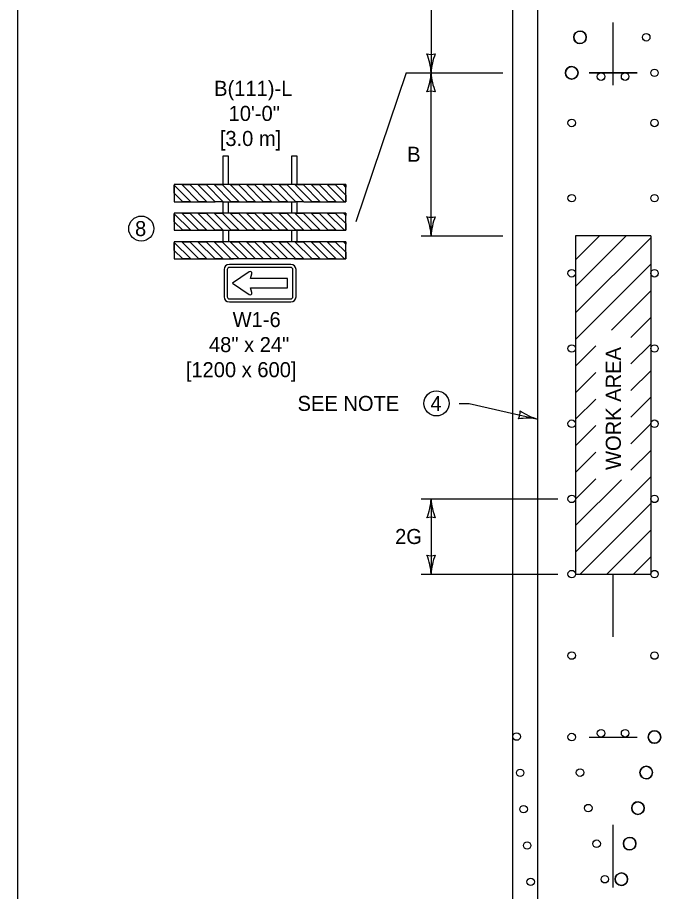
# Model space of a CAD drawing. Extents: x 49991.4 to 50021, y 49987.6 to 50011.4.
# Drawn here: x 50000.336 to 50002.917, y 50003.955 to 50007.442 of the extents above; entities that cross this region are included whole.
import ezdxf

# ---------------------------------------------------------------- set-up
doc = ezdxf.new("R2010")
doc.units = 0
for name, color, linetype in [('Level 1', 7, 'Continuous'), ('Level 2', 7, 'Continuous'), ('Level 3', 7, 'Continuous')]:
    doc.layers.add(name, color=color, linetype=linetype)

msp = doc.modelspace()

# ---------------------------------------------------------------- linework, layer by layer
at = {"layer": 'Level 1'}
for p, q in [((50002.3115, 50000.5714), (50002.3115, 50010.7538)), ((50002.4115, 50000.5714), (50002.4115, 50010.7538)), ((50002.7115, 50007.1716), (50002.7115, 50007.4216)), ((50002.6155, 50007.2214), (50002.7115, 50007.2214)), ((50002.7115, 50007.2214), (50002.6155, 50007.2214)), ((50002.7115, 50007.2214), (50002.8075, 50007.2214)), ((50002.8075, 50007.2214), (50002.7115, 50007.2214)), ((50000.9612, 50006.7728), (50001.0271, 50006.7069)), ((50000.9612, 50006.7728), (50001.0271, 50006.7069)), ((50000.9909, 50006.7753), (50001.0593, 50006.7069)), ((50001.0593, 50006.7069), (50000.9909, 50006.7753)), ((50001.0231, 50006.7753), (50001.0915, 50006.7069)), ((50001.0231, 50006.7753), (50001.0915, 50006.7069)), ((50001.0554, 50006.7753), (50001.1238, 50006.7069)), ((50001.1238, 50006.7069), (50001.0554, 50006.7753)), ((50001.0876, 50006.7753), (50001.156, 50006.7069)), ((50001.0876, 50006.7753), (50001.156, 50006.7069)), ((50001.1199, 50006.7753), (50001.1883, 50006.7069)), ((50001.1883, 50006.7069), (50001.1199, 50006.7753)), ((50001.1521, 50006.7753), (50001.2205, 50006.7069)), ((50001.1521, 50006.7753), (50001.2205, 50006.7069)), ((50001.1843, 50006.7753), (50001.2527, 50006.7069)), ((50001.2527, 50006.7069), (50001.1843, 50006.7753)), ((50001.2166, 50006.7753), (50001.285, 50006.7069)), ((50001.2166, 50006.7753), (50001.285, 50006.7069)), ((50001.2488, 50006.7753), (50001.3172, 50006.7069)), ((50001.3172, 50006.7069), (50001.2488, 50006.7753)), ((50001.2811, 50006.7753), (50001.3495, 50006.7069)), ((50001.2811, 50006.7753), (50001.3495, 50006.7069)), ((50001.3133, 50006.7753), (50001.3817, 50006.7069)), ((50001.3817, 50006.7069), (50001.3133, 50006.7753)), ((50001.3455, 50006.7753), (50001.4139, 50006.7069)), ((50001.3455, 50006.7753), (50001.4139, 50006.7069)), ((50001.3778, 50006.7753), (50001.4462, 50006.7069)), ((50001.4462, 50006.7069), (50001.3778, 50006.7753)), ((50001.41, 50006.7753), (50001.4784, 50006.7069)), ((50001.41, 50006.7753), (50001.4784, 50006.7069)), ((50001.4422, 50006.7753), (50001.5106, 50006.7069)), ((50001.5106, 50006.7069), (50001.4422, 50006.7753)), ((50001.4745, 50006.7753), (50001.5429, 50006.7069)), ((50001.4745, 50006.7753), (50001.5429, 50006.7069)), ((50001.5067, 50006.7753), (50001.5751, 50006.7069)), ((50001.5751, 50006.7069), (50001.5067, 50006.7753)), ((50001.539, 50006.7753), (50001.6074, 50006.7069)), ((50001.539, 50006.7753), (50001.6074, 50006.7069)), ((50001.5712, 50006.7753), (50001.6396, 50006.7069)), ((50001.6396, 50006.7069), (50001.5712, 50006.7753)), ((50001.6034, 50006.7753), (50001.6452, 50006.7336)), ((50001.6034, 50006.7753), (50001.6452, 50006.7336)), ((50001.6357, 50006.7753), (50001.6452, 50006.7658)), ((50001.6452, 50006.7658), (50001.6357, 50006.7753)), ((50000.9612, 50006.7406), (50000.9948, 50006.7069)), ((50000.9948, 50006.7069), (50000.9612, 50006.7406)), ((50000.9612, 50006.6588), (50001.0271, 50006.593)), ((50000.9612, 50006.6588), (50001.0271, 50006.593)), ((50000.9909, 50006.6614), (50001.0593, 50006.593)), ((50001.0593, 50006.593), (50000.9909, 50006.6614)), ((50001.0231, 50006.6614), (50001.0915, 50006.593)), ((50001.0231, 50006.6614), (50001.0915, 50006.593)), ((50001.0554, 50006.6614), (50001.1238, 50006.593)), ((50001.1238, 50006.593), (50001.0554, 50006.6614)), ((50001.0876, 50006.6614), (50001.156, 50006.593)), ((50001.0876, 50006.6614), (50001.156, 50006.593)), ((50001.1199, 50006.6614), (50001.1883, 50006.593)), ((50001.1521, 50006.6614), (50001.2205, 50006.593)), ((50001.1843, 50006.6614), (50001.2527, 50006.593)), ((50001.2166, 50006.6614), (50001.285, 50006.593)), ((50001.2488, 50006.6614), (50001.3172, 50006.593)), ((50001.2811, 50006.6614), (50001.3495, 50006.593)), ((50001.3133, 50006.6614), (50001.3817, 50006.593)), ((50001.3455, 50006.6614), (50001.4139, 50006.593)), ((50001.3778, 50006.6614), (50001.44, 50006.5991)), ((50001.41, 50006.6614), (50001.44, 50006.6313)), ((50001.4422, 50006.6614), (50001.5106, 50006.593)), ((50001.5106, 50006.593), (50001.4422, 50006.6614)), ((50001.4745, 50006.6614), (50001.5429, 50006.593)), ((50001.4745, 50006.6614), (50001.5429, 50006.593)), ((50001.5067, 50006.6614), (50001.5751, 50006.593)), ((50001.5751, 50006.593), (50001.5067, 50006.6614)), ((50001.539, 50006.6614), (50001.6074, 50006.593)), ((50001.539, 50006.6614), (50001.6074, 50006.593)), ((50001.5712, 50006.6614), (50001.6396, 50006.593)), ((50001.6396, 50006.593), (50001.5712, 50006.6614)), ((50001.6034, 50006.6614), (50001.6452, 50006.6197)), ((50001.6034, 50006.6614), (50001.6452, 50006.6197)), ((50001.6357, 50006.6614), (50001.6452, 50006.6519)), ((50001.6452, 50006.6519), (50001.6357, 50006.6614)), ((50000.9612, 50006.6266), (50000.9948, 50006.593)), ((50000.9948, 50006.593), (50000.9612, 50006.6266)), ((50001.44, 50006.6313), (50001.4784, 50006.593)), ((50001.1778, 50006.593), (50001.1778, 50006.5474)), ((50001.4286, 50006.593), (50001.4286, 50006.5474)), ((50001.44, 50006.5991), (50001.4462, 50006.593)), ((50002.5615, 50006.5714), (50002.5615, 50005.2214)), ((50002.5615, 50006.3694), (50002.7634, 50006.5714)), ((50002.5615, 50006.4755), (50002.6574, 50006.5714)), ((50002.8615, 50006.5714), (50002.5615, 50006.5714)), ((50002.5615, 50006.2634), (50002.8615, 50006.5634)), ((50002.8615, 50006.5714), (50002.8615, 50005.2214)), ((50000.9612, 50006.5449), (50001.0271, 50006.479)), ((50000.9612, 50006.5449), (50001.0271, 50006.479)), ((50000.9909, 50006.5474), (50001.0593, 50006.479)), ((50001.0593, 50006.479), (50000.9909, 50006.5474)), ((50001.0231, 50006.5474), (50001.0915, 50006.479)), ((50001.0231, 50006.5474), (50001.0915, 50006.479)), ((50001.0554, 50006.5474), (50001.1238, 50006.479)), ((50001.1238, 50006.479), (50001.0554, 50006.5474)), ((50001.0876, 50006.5474), (50001.156, 50006.479)), ((50001.0876, 50006.5474), (50001.156, 50006.479)), ((50001.1199, 50006.5474), (50001.1883, 50006.479)), ((50001.1521, 50006.5474), (50001.2205, 50006.479)), ((50001.1846, 50006.5474), (50001.253, 50006.479)), ((50001.2168, 50006.5474), (50001.2852, 50006.479)), ((50001.249, 50006.5474), (50001.3174, 50006.479)), ((50001.2812, 50006.5474), (50001.3496, 50006.479)), ((50001.3134, 50006.5474), (50001.3818, 50006.479)), ((50001.3456, 50006.5474), (50001.414, 50006.479)), ((50001.3778, 50006.5474), (50001.4462, 50006.479)), ((50001.41, 50006.5474), (50001.4784, 50006.479)), ((50001.4422, 50006.5474), (50001.5106, 50006.479)), ((50001.5106, 50006.479), (50001.4422, 50006.5474)), ((50001.4745, 50006.5474), (50001.5429, 50006.479)), ((50001.4745, 50006.5474), (50001.5429, 50006.479)), ((50001.5067, 50006.5474), (50001.5751, 50006.479)), ((50001.5751, 50006.479), (50001.5067, 50006.5474)), ((50001.539, 50006.5474), (50001.6074, 50006.479)), ((50001.539, 50006.5474), (50001.6074, 50006.479)), ((50001.5712, 50006.5474), (50001.6396, 50006.479)), ((50001.6396, 50006.479), (50001.5712, 50006.5474)), ((50001.6034, 50006.5474), (50001.6452, 50006.5057)), ((50001.6034, 50006.5474), (50001.6452, 50006.5057)), ((50001.6357, 50006.5474), (50001.6452, 50006.5379)), ((50001.6452, 50006.5379), (50001.6357, 50006.5474)), ((50000.9612, 50006.5126), (50000.9948, 50006.479)), ((50000.9948, 50006.479), (50000.9612, 50006.5126)), ((50001.1664, 50006.479), (50001.1977, 50006.479)), ((50001.4258, 50006.479), (50001.1807, 50006.479)), ((50001.4462, 50006.479), (50001.4063, 50006.479)), ((50001.4258, 50006.4572), (50001.1807, 50006.4572)), ((50001.4258, 50006.4448), (50001.1807, 50006.4448)), ((50002.5615, 50006.1573), (50002.8615, 50006.4573)), ((50001.1597, 50006.4363), (50001.1597, 50006.328)), ((50001.1721, 50006.4363), (50001.1721, 50006.328)), ((50001.2602, 50006.4278), (50001.1937, 50006.3821)), ((50001.2644, 50006.4004), (50001.2707, 50006.42)), ((50001.4343, 50006.328), (50001.4343, 50006.4363)), ((50001.4467, 50006.328), (50001.4467, 50006.4363)), ((50001.1937, 50006.3821), (50001.2602, 50006.3364)), ((50001.4127, 50006.4004), (50001.2644, 50006.4004)), ((50001.4127, 50006.3639), (50001.4127, 50006.4004)), ((50001.2707, 50006.3443), (50001.2644, 50006.3639)), ((50001.2644, 50006.3639), (50001.2746, 50006.3639)), ((50001.2746, 50006.3639), (50001.4127, 50006.3639)), ((50002.7051, 50006.1948), (50002.8615, 50006.3512)), ((50001.1807, 50006.3194), (50001.4258, 50006.3194)), ((50001.1807, 50006.307), (50001.4258, 50006.307)), ((50002.7823, 50006.166), (50002.8615, 50006.2452)), ((50002.5615, 50006.0512), (50002.6423, 50006.132)), ((50002.7823, 50006.0599), (50002.8615, 50006.1391)), ((50002.5615, 50005.9452), (50002.6423, 50006.026)), ((50002.7823, 50005.9538), (50002.8615, 50006.033)), ((50002.7823, 50005.8478), (50002.8615, 50005.927)), ((50002.5615, 50005.8391), (50002.6423, 50005.9199)), ((50002.7823, 50005.7417), (50002.8615, 50005.8209)), ((50002.5615, 50005.733), (50002.6423, 50005.8138)), ((50002.7823, 50005.6356), (50002.8615, 50005.7148)), ((50002.5615, 50005.627), (50002.6423, 50005.7078)), ((50002.5615, 50005.3088), (50002.8615, 50005.6088)), ((50002.5615, 50005.5209), (50002.6423, 50005.6017)), ((50002.5615, 50005.4148), (50002.7446, 50005.5979)), ((50002.5802, 50005.2214), (50002.8615, 50005.5027)), ((50002.6862, 50005.2214), (50002.8615, 50005.3966)), ((50002.7923, 50005.2214), (50002.8615, 50005.2906)), ((50002.5615, 50005.2214), (50002.8615, 50005.2214)), ((50002.7115, 50004.9716), (50002.7115, 50005.2216)), ((50002.6155, 50004.5714), (50002.7115, 50004.5714)), ((50002.7115, 50004.5714), (50002.8075, 50004.5714)), ((50002.7115, 50003.9716), (50002.7115, 50004.2216))]:
    msp.add_line(p, q, dxfattribs=at)
msp.add_lwpolyline([(50008.6146, 50011.2628), (50000.3356, 50011.2628), (50000.3356, 50000.0624), (50008.6146, 50000.0624)], close=True, dxfattribs=at)
for points in [[(50001.1778, 50006.7754), (50001.1778, 50006.8894), (50001.155, 50006.8894), (50001.155, 50006.7754)], [(50001.4514, 50006.7754), (50001.4514, 50006.8894), (50001.4286, 50006.8894), (50001.4286, 50006.7754)], [(50001.4784, 50006.7069), (50001.6452, 50006.7069), (50001.6452, 50006.7753), (50000.9612, 50006.7753), (50000.9612, 50006.7069), (50001.1238, 50006.7069)], [(50000.9612, 50006.7406), (50000.9612, 50006.7728)], [(50000.9909, 50006.7753), (50001.0231, 50006.7753)], [(50001.0554, 50006.7753), (50001.0876, 50006.7753)], [(50001.1199, 50006.7753), (50001.1521, 50006.7753)], [(50001.1843, 50006.7753), (50001.2166, 50006.7753)], [(50001.2488, 50006.7753), (50001.2811, 50006.7753)], [(50001.3133, 50006.7753), (50001.3455, 50006.7753)], [(50001.3778, 50006.7753), (50001.41, 50006.7753)], [(50001.4422, 50006.7753), (50001.4745, 50006.7753)], [(50001.5067, 50006.7753), (50001.539, 50006.7753)], [(50001.5712, 50006.7753), (50001.6034, 50006.7753)], [(50001.6357, 50006.7753), (50001.6452, 50006.7753), (50001.6452, 50006.7658)], [(50001.6452, 50006.7336), (50001.6452, 50006.7069), (50001.6396, 50006.7069)], [(50001.0271, 50006.7069), (50000.9948, 50006.7069)], [(50001.0915, 50006.7069), (50001.0593, 50006.7069)], [(50001.156, 50006.7069), (50001.1238, 50006.7069)], [(50001.155, 50006.7069), (50001.155, 50006.6614)], [(50001.156, 50006.7069), (50001.4462, 50006.7069)], [(50001.1778, 50006.6614), (50001.1778, 50006.7069)], [(50001.2205, 50006.7069), (50001.1883, 50006.7069)], [(50001.285, 50006.7069), (50001.2527, 50006.7069)], [(50001.3495, 50006.7069), (50001.3172, 50006.7069)], [(50001.4139, 50006.7069), (50001.3817, 50006.7069)], [(50001.4286, 50006.7069), (50001.4286, 50006.6614)], [(50001.4784, 50006.7069), (50001.4462, 50006.7069)], [(50001.4514, 50006.6614), (50001.4514, 50006.7069)], [(50001.5429, 50006.7069), (50001.5106, 50006.7069)], [(50001.6074, 50006.7069), (50001.5751, 50006.7069)], [(50001.44, 50006.593), (50001.6452, 50006.593), (50001.6452, 50006.6614), (50000.9612, 50006.6614), (50000.9612, 50006.593), (50001.44, 50006.593)], [(50000.9612, 50006.6266), (50000.9612, 50006.6588)], [(50000.9909, 50006.6614), (50001.0231, 50006.6614)], [(50001.0554, 50006.6614), (50001.0876, 50006.6614)], [(50001.2205, 50006.593), (50001.1883, 50006.593), (50001.1199, 50006.6614), (50001.1521, 50006.6614), (50001.2205, 50006.593)], [(50001.285, 50006.593), (50001.2527, 50006.593), (50001.1843, 50006.6614), (50001.2166, 50006.6614), (50001.285, 50006.593)], [(50001.3495, 50006.593), (50001.3172, 50006.593), (50001.2488, 50006.6614), (50001.2811, 50006.6614), (50001.3495, 50006.593)], [(50001.4139, 50006.593), (50001.3817, 50006.593), (50001.3133, 50006.6614), (50001.3455, 50006.6614), (50001.4139, 50006.593)], [(50001.3778, 50006.6614), (50001.41, 50006.6614), (50001.44, 50006.6313), (50001.4784, 50006.593), (50001.4514, 50006.593), (50001.4462, 50006.593), (50001.44, 50006.5991), (50001.3778, 50006.6614)], [(50001.4422, 50006.6614), (50001.4745, 50006.6614)], [(50001.5067, 50006.6614), (50001.539, 50006.6614)], [(50001.5712, 50006.6614), (50001.6034, 50006.6614)], [(50001.6357, 50006.6614), (50001.6452, 50006.6614), (50001.6452, 50006.6519)], [(50001.6452, 50006.6197), (50001.6452, 50006.593), (50001.6396, 50006.593)], [(50001.0271, 50006.593), (50000.9948, 50006.593)], [(50001.0915, 50006.593), (50001.0593, 50006.593)], [(50001.156, 50006.593), (50001.1238, 50006.593)], [(50001.155, 50006.593), (50001.155, 50006.5474)], [(50001.4514, 50006.5474), (50001.4514, 50006.593)], [(50001.5429, 50006.593), (50001.5106, 50006.593)], [(50001.6074, 50006.593), (50001.5751, 50006.593)], [(50001.44, 50006.5474), (50000.9612, 50006.5474), (50000.9612, 50006.479), (50001.1664, 50006.479)], [(50000.9612, 50006.5126), (50000.9612, 50006.5449)], [(50000.9909, 50006.5474), (50001.0231, 50006.5474)], [(50001.0554, 50006.5474), (50001.0876, 50006.5474)], [(50001.2205, 50006.479), (50001.1977, 50006.479), (50001.1883, 50006.479), (50001.1199, 50006.5474), (50001.1521, 50006.5474), (50001.2205, 50006.479)], [(50001.2852, 50006.479), (50001.253, 50006.479), (50001.1846, 50006.5474), (50001.2168, 50006.5474), (50001.2852, 50006.479)], [(50001.3496, 50006.479), (50001.3174, 50006.479), (50001.249, 50006.5474), (50001.2812, 50006.5474), (50001.3496, 50006.479)], [(50001.414, 50006.479), (50001.4063, 50006.479), (50001.3818, 50006.479), (50001.3134, 50006.5474), (50001.3456, 50006.5474), (50001.414, 50006.479)], [(50001.3778, 50006.5474), (50001.41, 50006.5474), (50001.4784, 50006.479), (50001.4462, 50006.479), (50001.3778, 50006.5474)], [(50001.44, 50006.479), (50001.6452, 50006.479), (50001.6452, 50006.5474), (50001.44, 50006.5474)], [(50001.4422, 50006.5474), (50001.4745, 50006.5474)], [(50001.5067, 50006.5474), (50001.539, 50006.5474)], [(50001.5712, 50006.5474), (50001.6034, 50006.5474)], [(50001.6357, 50006.5474), (50001.6452, 50006.5474), (50001.6452, 50006.5379)], [(50001.0271, 50006.479), (50000.9948, 50006.479)], [(50001.0915, 50006.479), (50001.0593, 50006.479)], [(50001.156, 50006.479), (50001.1238, 50006.479)], [(50001.5429, 50006.479), (50001.5106, 50006.479)], [(50001.6074, 50006.479), (50001.5751, 50006.479)], [(50001.6452, 50006.5057), (50001.6452, 50006.479), (50001.6396, 50006.479)]]:
    msp.add_lwpolyline(points, dxfattribs=at)
for centre, radius in [((50002.5795, 50007.3632), 0.025), ((50002.8435, 50007.3632), 0.015), ((50002.8435, 50007.3632), 0.015), ((50002.5465, 50007.2214), 0.025), ((50002.5465, 50007.2214), 0.025), ((50002.5465, 50007.2214), 0.025), ((50002.5465, 50007.2214), 0.025), ((50002.6635, 50007.2061), 0.0152), ((50002.6635, 50007.2062), 0.0152), ((50002.7595, 50007.2061), 0.0152), ((50002.7595, 50007.2062), 0.0152), ((50002.8765, 50007.2214), 0.015), ((50002.8765, 50007.2214), 0.015), ((50002.5465, 50007.0214), 0.015), ((50002.8765, 50007.0214), 0.015), ((50002.5465, 50006.7214), 0.015), ((50002.8765, 50006.7214), 0.015), ((50002.5465, 50006.4214), 0.015), ((50002.8765, 50006.4214), 0.015), ((50002.5465, 50006.1214), 0.015), ((50002.8765, 50006.1214), 0.015), ((50002.5465, 50005.8214), 0.015), ((50002.8765, 50005.8214), 0.015), ((50002.5465, 50005.5214), 0.015), ((50002.8765, 50005.5214), 0.015), ((50002.5465, 50005.2214), 0.015), ((50002.8765, 50005.2214), 0.015), ((50002.5465, 50004.8964), 0.015), ((50002.8765, 50004.8964), 0.015), ((50002.6635, 50004.5866), 0.0152), ((50002.7595, 50004.5866), 0.0152), ((50002.8765, 50004.5714), 0.025), ((50002.8765, 50004.5714), 0.025), ((50002.8765, 50004.5714), 0.025), ((50002.3266, 50004.5733), 0.015), ((50002.5465, 50004.5714), 0.015), ((50002.3406, 50004.4284), 0.015), ((50002.5795, 50004.4295), 0.015), ((50002.5795, 50004.4295), 0.015), ((50002.8435, 50004.4295), 0.025), ((50002.3546, 50004.2834), 0.015), ((50002.6125, 50004.2877), 0.015), ((50002.6125, 50004.2877), 0.015), ((50002.8105, 50004.2877), 0.025), ((50002.3686, 50004.1385), 0.015), ((50002.6455, 50004.1458), 0.015), ((50002.6455, 50004.1458), 0.015), ((50002.7774, 50004.1459), 0.025), ((50002.3826, 50003.9935), 0.015), ((50002.3826, 50003.9935), 0.015), ((50002.6784, 50004.004), 0.015), ((50002.7444, 50004.0041), 0.025)]:
    msp.add_circle(centre, radius, dxfattribs=at)
for centre, radius, start, end in [((50002.5795, 50007.3632), 0.025, 21.4014, 201.4014), ((50002.5795, 50007.3632), 0.025, 201.4014, 21.4014), ((50002.5465, 50007.2214), 0.025, 0, 180), ((50002.5465, 50007.2214), 0.025, 0, 180), ((50002.5465, 50007.2214), 0.025, 0, 180), ((50002.5465, 50007.2214), 0.025, 21.4014, 201.4014), ((50002.5465, 50007.2214), 0.025, 180, 0), ((50002.5465, 50007.2214), 0.025, 180, 0), ((50002.5465, 50007.2214), 0.025, 180, 0), ((50002.5465, 50007.2214), 0.025, 201.4014, 21.4014), ((50001.1807, 50006.4363), 0.0209, 90, 180), ((50001.1807, 50006.4363), 0.00855, 90, 180), ((50001.4258, 50006.4363), 0.0209, 0, 90), ((50001.4258, 50006.4363), 0.00855, 0, 90), ((50001.2641, 50006.4221), 0.00695, 342.0418, 124.5194), ((50001.2641, 50006.3422), 0.00695, 235.4806, 17.9582), ((50001.1807, 50006.328), 0.0209, 180, 270), ((50001.1807, 50006.328), 0.00855, 180, 270), ((50001.4258, 50006.328), 0.00855, 270, 360), ((50001.4258, 50006.328), 0.0209, 270, 360), ((50002.8765, 50004.5714), 0.025, 0, 180), ((50002.8765, 50004.5714), 0.025, 0, 180), ((50002.8765, 50004.5714), 0.025, 21.4014, 201.4014), ((50002.8765, 50004.5714), 0.025, 180, 0), ((50002.8765, 50004.5714), 0.025, 180, 0), ((50002.8765, 50004.5714), 0.025, 201.4014, 21.4014), ((50002.8435, 50004.4295), 0.025, 21.4014, 201.4014), ((50002.8435, 50004.4295), 0.025, 201.4014, 21.4014), ((50002.8105, 50004.2877), 0.025, 21.4014, 201.4014), ((50002.8105, 50004.2877), 0.025, 201.4014, 21.4014), ((50002.7774, 50004.1459), 0.025, 21.4014, 201.4014), ((50002.7774, 50004.1459), 0.025, 201.4014, 21.4014), ((50002.7444, 50004.0041), 0.025, 21.4014, 201.4014), ((50002.7444, 50004.0041), 0.025, 201.4014, 21.4014)]:
    msp.add_arc(centre, radius, start, end, dxfattribs=at)
at = {"layer": 'Level 2'}
for centre in [(50000.8295, 50006.5999), (50002.0068, 50005.9025)]:
    msp.add_circle(centre, 0.0501, dxfattribs=at)
at = {"layer": 'Level 3'}
for p, q in [((50001.9855, 50007.9305), (50001.9855, 50007.2214)), ((50001.8855, 50007.2214), (50001.6851, 50006.6272)), ((50001.8855, 50007.2214), (50002.2715, 50007.2214)), ((50001.9855, 50006.5714), (50001.9855, 50007.2214)), ((50001.9455, 50006.5714), (50002.2715, 50006.5714)), ((50002.0969, 50005.9025), (50002.1369, 50005.9025)), ((50002.1369, 50005.9025), (50002.4115, 50005.8397)), ((50001.9455, 50005.5214), (50002.4915, 50005.5214)), ((50001.9855, 50005.5214), (50001.9855, 50005.2214)), ((50001.9455, 50005.2214), (50002.4915, 50005.2214))]:
    msp.add_line(p, q, dxfattribs=at)
for centre, radius, start, end in [((50001.9855, 50007.3496), 0.0548, 252.1388, 287.8612), ((50001.7528, 50007.2099), 0.233, 2.8273, 22.0772), ((50002.2076, 50007.2122), 0.2223, 157.456, 177.6395), ((50001.7634, 50007.2305), 0.2223, 337.456, 357.6395), ((50002.2182, 50007.2329), 0.233, 182.8273, 202.0772), ((50001.9855, 50007.0932), 0.0548, 72.1388, 107.8612), ((50001.9855, 50006.6996), 0.0548, 252.1388, 287.8612), ((50001.7528, 50006.5599), 0.233, 2.8273, 22.0772), ((50002.2076, 50006.5622), 0.2223, 157.456, 177.6395), ((50002.2865, 50005.8683), 0.0548, 329.2424, 4.9647), ((50002.47, 50006.0542), 0.2223, 234.5596, 254.7431), ((50002.3708, 50005.6103), 0.233, 79.9309, 99.1807), ((50001.7634, 50005.5305), 0.2223, 337.456, 357.6395), ((50002.2182, 50005.5329), 0.233, 182.8273, 202.0772), ((50001.9855, 50005.3932), 0.0548, 72.1388, 107.8612), ((50001.9855, 50005.3496), 0.0548, 252.1388, 287.8612), ((50001.7528, 50005.2099), 0.233, 2.8273, 22.0772), ((50002.2076, 50005.2122), 0.2223, 157.456, 177.6395)]:
    msp.add_arc(centre, radius, start, end, dxfattribs=at)

# ---------------------------------------------------------------- texts
at = {"layer": 'Level 2'}
for s, p in [('B(111)-L', (50001.12, 50007.1294)), ('10\'-0"', (50001.1778, 50007.0294)), ('[3.0 m]', (50001.1425, 50006.9294)), ('B', (50001.89, 50006.8664)), ('8', (50000.8045, 50006.5699)), ('W1-6', (50001.1938, 50006.207)), ('48" x 24"', (50001.0994, 50006.107)), ('[1200 x 600]', (50001.0069, 50006.007)), ('SEE NOTE', (50001.4527, 50005.8724)), ('4', (50001.9829, 50005.8725)), ('2G', (50001.8419, 50005.3414))]:
    msp.add_text(s, height=0.06, dxfattribs=at).set_placement(p)
msp.add_text('WORK AREA', height=0.06, rotation=90, dxfattribs=at).set_placement((50002.7423, 50005.6368))

doc.saveas('drawing.dxf')
